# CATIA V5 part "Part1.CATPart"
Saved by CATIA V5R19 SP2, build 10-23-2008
Part number: Part1
Bounding box of the stored display mesh (mm): x -44.968 to 44.968, y 0 to 180, z -44.933 to 47.5
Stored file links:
  C:\Users\ismai\Desktop\catia\Part1.CATPart
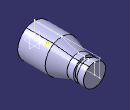
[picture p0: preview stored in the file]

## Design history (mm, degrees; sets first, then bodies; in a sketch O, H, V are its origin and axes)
Body1 (main body)
  Sketch1 on yz-plane, origin (0, 0, 0), H (0, 1, 0), V (0, 0, 1)
    line L1 (0, 0) -> (0, 45)
    line L2 (0, 45) -> (75, 45)
    line L3 (75, 45) -> (120, 30)
    point P3 (120, 30)
    line L4 (120, 30) -> (137.5, 30)
    line L5 (137.5, 30) -> (137.5, 25)
    line L6 (137.5, 25) -> (147.5, 25)
    line L7 (147.5, 25) -> (147.5, 30)
    point P7 (147.5, 30)
    line L8 (147.5, 30) -> (165, 30)
    line L9 (165, 30) -> (165, 0)
    point P9 (165, 0)
    line L10 (165, 0) -> (0, 0)
    length L9 = 30
    length L1 = 45
    length L2 = 75
    length L10 = 165
    distance L7 L9 = 17.5
    length L6 = 10
    distance L10 L6 = 25
    distance P3 L9 = 45
    vertical: L1 V, L5 V, L7 V, L9 V
    horizontal: L2 H, L4 H, L6 H, L8 H, L10 H
    coincidence: P7 L4, P9 H
  Shaft1: profile Sketch1, axis Sketch1.L10, angle 360
Body2
  Sketch2 on yz-plane, origin (0, 0, 0), H (0, 1, 0), V (0, 0, 1)
    line L1 (0, 0) -> (180, 0)
    line L2 (180, 0) -> (180, 47.5)
    line L3 (180, 47.5) -> (0, 47.5)
    line L4 (0, 47.5) -> (0, 0)
    length L3 = 180
    length L2 = 47.5
    horizontal: L1 H, L3 H
    vertical: L2 V, L4 V
  Shaft2: profile Sketch2, axis Sketch2.L1, angle 360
